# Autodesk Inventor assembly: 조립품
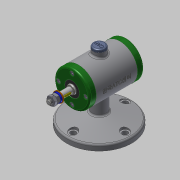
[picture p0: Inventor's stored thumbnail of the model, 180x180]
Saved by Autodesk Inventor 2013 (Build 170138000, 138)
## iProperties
Created: 2018-12
Part Number: 조립품
Document SubType Name: Assembly
Designer: Administrator
Author: Administrator
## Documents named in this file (15)
- C:\Users\Administrator\Desktop\481207V1047\조립품.iam
- C:\Users\Administrator\Desktop\481207V1047\본체.ipt
- C:\Users\Administrator\Desktop\481207V1047\V벨트풀리.ipt
- C:\Users\Administrator\Desktop\481207V1047\고무캡.ipt
- C:\Users\Administrator\Desktop\481207V1047\너트 M8.ipt
- 너트 M8.ipt
- C:\Users\Administrator\Desktop\481207V1047\뒤커버.ipt
- C:\Users\Administrator\Desktop\481207V1047\베어링 15 x 32 x 9.ipt
- C:\Users\Administrator\Desktop\481207V1047\볼트 M4 x 12.ipt
- C:\Users\Administrator\Desktop\481207V1047\스프링와셔 8.ipt
- C:\Users\Administrator\Desktop\481207V1047\앞커버.ipt
- C:\Users\Administrator\Desktop\481207V1047\오일 실 15 25 7.ipt
- C:\Users\Administrator\Desktop\481207V1047\와셔 8x17.ipt
- C:\Users\Administrator\Desktop\481207V1047\축.ipt
- C:\Users\Administrator\Desktop\481207V1047\키 3 x 3 x 12.ipt
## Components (2 placed, 2 different names)
1. V벨트풀리:1
2. 고무캡:1
